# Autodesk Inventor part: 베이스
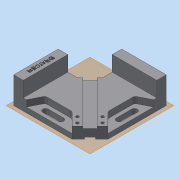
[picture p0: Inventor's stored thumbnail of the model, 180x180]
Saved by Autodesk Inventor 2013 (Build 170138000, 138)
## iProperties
Created: 2019-04
Part Number: 베이스
Material: 일반
Document SubType Name: Modeling
Designer: dgall
Density: 1 g/cm^3
Author: dgall
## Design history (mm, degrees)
sketch "스케치2"
  geometry: L1 (-60, 60)-(60, 60); L2 (60, 60)-(60, -60); L3 (60, -60)-(-60, -60); L4 (-60, -60)-(-60, 60); 3 further points
  constraints: 8 end point, 2 midpoint, 2 parallel, 1 horizontal, 1 horizontal alignment, 1 perpendicular, 1 vertical alignment
  dimensions: "d3" = 120 distance of L1.start L1.end; "d5" = 120 distance of L1.end L2.end
extrude "돌출1" new body sketch "스케치2" distance "d6" = 42; taper "d7" = 0 deg
sketch "스케치3"
  geometry: L1 (60, 60)-(-60, 60) reference; L2 (-60, 60)-(-60, -60) reference; L3 (-60, -60)-(60, -60) reference; L4 (-45, 45)-(63.533, 45); L5 (63.533, 45)-(63.533, -84.63); L6 (63.533, -84.63)-(-45, -84.63); L7 (-45, -84.63)-(-45, 45); 1 further point
  constraints: 8 end point, 2 parallel, 2 perpendicular
  dimensions: "d8" = 15 distance between parallel lines of L7 L2; "d9" = 15 distance between parallel lines of L1 L4
extrude "돌출2" cut sketch "스케치3" distance "d10" = 24; taper "d11" = 0 deg
sketch "스케치4"
  geometry: L1 (60, -60)-(31.716, -60); L2 (60, -60)-(-60, -60) reference; L3 (31.716, -60)-(60, -31.716); L4 (60, 60)-(60, -60) reference; L5 (60, -60)-(60, -31.716); L6 (60, -60)-(45.858, -45.858); 1 further point
  constraints: 8 end point, 2 point on line, 1 collinear, 1 midpoint, 1 perpendicular
  dimensions: "d12" = 45 deg angle of L1 L6; "d13" = 20 distance of L1.start L6.end
extrude "돌출3" cut sketch "스케치4" distance "d14" = 24; taper "d15" = 0 deg
sketch "스케치5"
  geometry: L1 (31.716, -60)-(60, -31.716) reference; L2 (-45, -60)-(-45, 45) reference; L3 (45.858, -45.858)-(-45, 45); L4 (51.515, -40.201)-(-48.686, 60); L5 (60, 60)-(-60, 60) reference; L6 (40.201, -51.515)-(-60, 48.686); L7 (-60, -60)-(-60, 60) reference; L8 (-60, 48.686)-(-48.686, 60); L9 (40.201, -51.515)-(51.515, -40.201); L10 (60, -31.716)-(31.716, -60) reference; L11 (51.515, -40.201)-(40.201, -51.515); 1 further point
  constraints: 12 end point, 6 point on line, 2 collinear, 2 perpendicular, 2 symmetric about line, 1 midpoint, 1 parallel
  dimensions: "d16" = 8 distance between parallel lines of L3 L4
extrude "돌출4" cut sketch "스케치5" distance "d18" = 3.5; taper "d19" = 0 deg
sketch "스케치6"
  geometry: L1 (51.515, -40.201)-(40.201, -51.515) reference; L2 (45.858, -45.858)-(-19.903, 19.903); L3 (-60, 60)-(-10, 60); L4 (-10, 60)-(-10, 10); L5 (-10, 10)-(-60, 10); L6 (-60, 10)-(-60, 60); L7 (-19.903, 19.903)-(-10, 29.806); L8 (-19.903, 19.903)-(-29.806, 10); 1 further point
  constraints: 14 end point, 3 equal length, 3 perpendicular, 3 point on line, 1 horizontal, 1 midpoint
  dimensions: "d22" = 93 distance of L2.start L2.end; "d23" = 50 distance of L3.start L3.end
extrude "돌출5" cut sketch "스케치6" stored distance "d24" = 3.5; taper "d25" = 0 deg
sketch "스케치7"
  geometry: L1 (31.716, -60)-(-45, -60) reference; L2 (40.201, -51.515)-(-25.56, 14.246) reference; L3 (-40, -60)-(-30, -40); L4 (-30, -40)-(11.716, -40); L5 (11.716, -40)-(31.716, -60); L6 (-60, 10)-(-60, -60) reference; L7 (51.515, -40.201)-(40.201, -51.515) reference; L8 (45.858, -45.858)-(26.857, -26.857); L9 (45.858, -45.858)-(31.716, -60); L10 (31.716, -60)-(-40, -60); L11 (40, 30)-(40, -11.716); L12 (60, 40)-(40, 30); L13 (60, -31.716)-(60, 45); L14 (40, -11.716)-(60, -31.716); 1 further point
  constraints: 20 end point, 5 symmetric about line, 4 point on line, 2 parallel, 2 perpendicular, 1 midpoint
  dimensions: "d26" = 20 distance from line of L6 L3.start; "d27" = 20 distance between parallel lines of L1 L4; "d28" = 30 distance from line of L6 L3.end; "d29" = 20 distance of L8.start L5.end
extrude "돌출6" cut sketch "스케치7" distance "d30" = 10; taper "d31" = 0 deg
extrude "돌출7" cut sketch "스케치7" distance "d32" = 10; taper "d33" = 0 deg
sketch "스케치8"
  geometry: L1 (-12, 18)-(28, 18) reference; L2 (14, 15)-(2, 15); L3 (2, 15)-(2, 18); L4 (2, 18)-(14, 18); L5 (14, 18)-(14, 15); 2 further points
  constraints: 8 end point, 2 midpoint, 2 parallel, 1 horizontal, 1 perpendicular, 1 point on line
  dimensions: "d34" = 12 distance of L2.start L2.end; "d36" = 3 distance of L4.end L2.start
extrude "돌출8" cut sketch "스케치8" stored distance "d37" = 0; taper "d38" = 0 deg
sketch "스케치9" dims "d39" = 9
  geometry: L1 (31.716, -60)-(-40, -60) reference; L2 (-60, 10)-(-60, -60) reference; L3 (-20, -45.5)-(4, -45.5); L4 (4, -45.5)-(4, -54.5); L5 (4, -54.5)-(-20, -54.5); L6 (-20, -54.5)-(-20, -45.5); L7 (41.615, -50.101)-(50.101, -41.615) reference; L8 (45.858, -45.858)-(-19.253, 19.253); L9 (41.615, -50.101)-(-24.146, 15.66) reference; L10 (45.5, 20)-(45.5, -4); L11 (54.5, -4)-(54.5, 20); L12 (54.5, 20)-(45.5, 20); L13 (45.5, -4)-(54.5, -4); C1 r 4.5 at (4, -50); C2 r 4.5 at (50, -4); 4 further points
  constraints: 18 end point, 6 symmetric about line, 3 midpoint, 3 parallel, 2 centre point, 2 horizontal, 1 coincident, 1 horizontal alignment, 1 perpendicular, 1 vertical alignment, 6 other
  dimensions: "d41" = 40 distance from line of L2 point (-20, -50); "d42" = 10 distance from line of L1 point (-20, -50); "d43" = 24 distance of L3.start L3.end; "d44" = 9 diameter of C1
extrude "돌출9" cut sketch "스케치9" stored distance "d45" = 10; taper "d46" = 0 deg
extrude "돌출10" cut sketch "스케치9" stored distance "d47" = 10; taper "d48" = 0 deg
sketch "스케치10"
  geometry: L1 (11.716, -40)-(31.716, -60) reference; L2 (41.615, -50.101)-(50.101, -41.615) reference; L3 (45.858, -45.858)-(-19.903, 19.903); L4 (-15.66, 24.146)-(-24.146, 15.66) reference; L5 (41.615, -41.615)-(31.716, -51.515); L6 (31.716, -51.515)-(-25.241, 5.442); L7 (23.23, -43.029)-(33.13, -33.13); 5 further points
  constraints: 8 end point, 3 perpendicular, 3 point on line, 2 coincident, 2 midpoint, 2 symmetric about line
  dimensions: "d50" = 6 distance between parallel lines of L2 L5; "d51" = 14 distance between parallel lines of L3 L6; "d52" = 12 distance between parallel lines of L5 L7
hole "구멍1" sketch "스케치10" diameter "d53" = 4.5; stored, may be unused: countersink angle "d57" = 90 deg, drill point angle "d59" = 118 deg; dims "d54" = 6, "d55" = 4, "d56" = 2, "d58" = 8
hole "구멍2" sketch "스케치10" diameter "d60" = 4.5; stored, may be unused: countersink angle "d64" = 90 deg, drill point angle "d66" = 118 deg; dims "d61" = 6, "d62" = 4, "d63" = 2, "d65" = 8
sketch "스케치11"
  geometry: C1 r 2.25 at (-31.716, -51.515) reference; C2 r 2.25 at (-23.23, -43.029) reference; C3 r 2.25 at (-43.029, -23.23) reference; C4 r 2.25 at (-51.515, -31.716) reference; 5 further points
  constraints: 4 coincident
hole "구멍3" sketch "스케치11" diameter "d67" = 8; stored, may be unused: countersink angle "d71" = 90 deg, drill point angle "d73" = 0 deg; dims "d68" = 6, "d69" = 4, "d70" = 2, "d72" = 10
hole "구멍4" sketch "스케치11" diameter "d74" = 8; stored, may be unused: countersink angle "d78" = 90 deg, drill point angle "d80" = 0 deg; dims "d75" = 6, "d76" = 4, "d77" = 2, "d79" = 10
sketch "스케치12"
  geometry: L1 (-45, 10)-(-60, 10) reference; 2 further points
  constraints: 1 other
  dimensions: "d81" = 7.5 horizontal distance of point (-52.5, -25) L1.end; "d82" = 35 distance from line of L1 point (-52.5, -25)
feature "엠보싱1" sketch "스케치12" dims "d3" = 120, "d5" = 120, "d83" = 0.5, "d84" = 0
fillet "모깎기1" dims "d85" = 5
node "솔리드1"
